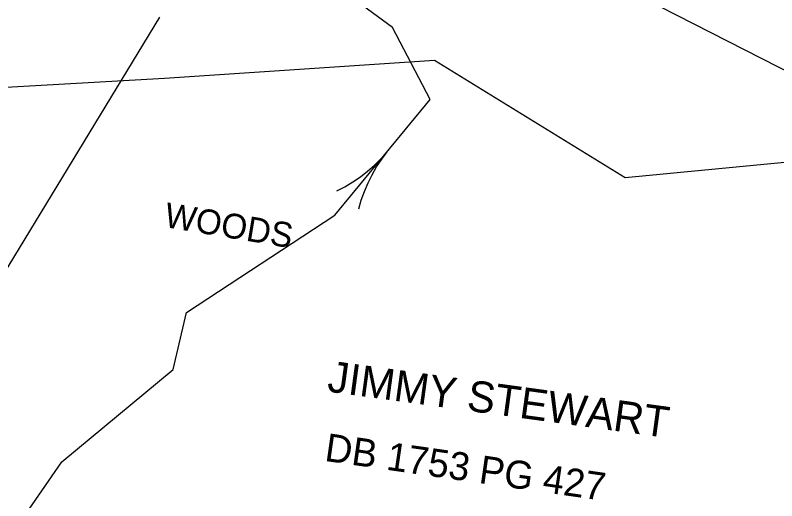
# Model space of a CAD drawing. Extents: x 1234385 to 1237843, y 694759 to 696635.
# Drawn here: x 1234890.4 to 1235013.1, y 695194.5 to 695272.7 of the extents above; entities that cross this region are included whole.
import ezdxf

# ---------------------------------------------------------------- set-up
doc = ezdxf.new("R2010")
doc.units = 0
for name, color, linetype in [('Exist Hydro Jurisdictional Stream or Body of Water', 7, 'Continuous'), ('Exist Hydro Stream Flow Arrow CELL', 7, 'Continuous'), ('Exist Property Deed Book Text', 7, 'Continuous'), ('Exist Property Owner Text', 7, 'Continuous'), ('Exist Right of Way Line', 7, 'Continuous'), ('Exist Roads EOP', 7, 'Continuous'), ('Exist Utilities Other Located Object Leader', 7, 'Continuous'), ('Exist Vegetation Woods Line', 7, 'Continuous'), ('Exist Vegetation Woods Line Text', 7, 'Continuous')]:
    doc.layers.add(name, color=color, linetype=linetype)

msp = doc.modelspace()

# ---------------------------------------------------------------- linework, layer by layer
at = {"layer": 'Exist Hydro Jurisdictional Stream or Body of Water'}
for points in [[(1234884.02, 695180.66), (1234897.94, 695200.74), (1234915.89, 695215.63), (1234918.03, 695224.8), (1234941.89, 695240.45), (1234957.27, 695259.09), (1234951.21, 695270.69), (1234942.31, 695277.23), (1234922.59, 695292.01)], [(1234944.11, 695289.59), (1234953.37, 695288.16), (1234962.33, 695289.23), (1234972.33, 695285.32), (1235018.75, 695261.57)]]:
    msp.add_lwpolyline(points, dxfattribs=at)
at = {"layer": 'Exist Hydro Stream Flow Arrow CELL'}
msp.add_line((1234947.16, 695246.79), (1234947.16, 695246.79), dxfattribs=at)
for points in [[(1234942.22, 695244.37), (1234943.54, 695245.03), (1234944.8, 695245.84), (1234946.03, 695246.65), (1234947.16, 695247.55), (1234948.27, 695248.53), (1234949.34, 695249.58), (1234950.33, 695250.66)], [(1234945.76, 695241.48), (1234946.15, 695242.89), (1234946.69, 695244.29), (1234947.25, 695245.66), (1234947.9, 695246.95), (1234948.64, 695248.23), (1234949.46, 695249.48), (1234950.33, 695250.66)]]:
    msp.add_lwpolyline(points, dxfattribs=at)
at = {"layer": 'Exist Right of Way Line'}
msp.add_arc((1234852.87, 694607.88), 686.2, 74.43765, 84.81729, dxfattribs=at)
at = {"layer": 'Exist Roads EOP'}
for points in [[(1234989.74, 695321.28), (1235032.63, 695310.76), (1235082.97, 695294.62), (1235134.25, 695274.48), (1235183.93, 695250.95), (1235232.11, 695225.68)], [(1234969.59, 695304.59), (1235025.45, 695292.96), (1235076.31, 695277.19), (1235126.22, 695256.57), (1235174.52, 695234.32), (1235222.25, 695208.99)]]:
    msp.add_spline(points, degree=3, dxfattribs=at)
at = {"layer": 'Exist Utilities Other Located Object Leader'}
msp.add_line((1234913.68, 695272.36), (1234865.56, 695193.27), dxfattribs=at)
at = {"layer": 'Exist Vegetation Woods Line'}
msp.add_lwpolyline([(1234846.34, 695211.66), (1234862.97, 695243.02), (1234869.05, 695259.98), (1234914.47, 695262.54), (1234957.97, 695265.42), (1234988.67, 695246.54), (1235065.72, 695253.96), (1235118.17, 695242.12), (1235189.82, 695216.84), (1235231.72, 695188.68), (1235232.28, 695138.59), (1235209.33, 695099.95), (1235186.38, 695079.79)], dxfattribs=at)

# ---------------------------------------------------------------- texts
at = {"layer": 'Exist Property Deed Book Text'}
msp.add_text('DB 1753 PG 427', height=4.5, rotation=351.8436, dxfattribs=at).set_placement((1234940.12, 695200.91))
at = {"layer": 'Exist Property Owner Text'}
msp.add_text('JIMMY STEWART', height=5, rotation=352.2161, dxfattribs=at).set_placement((1234940.55, 695212.08))
at = {"layer": 'Exist Vegetation Woods Line Text'}
msp.add_text('WOODS', height=4, rotation=350.4678, dxfattribs=at).set_placement((1234914.27, 695238.59))

doc.saveas('drawing.dxf')
